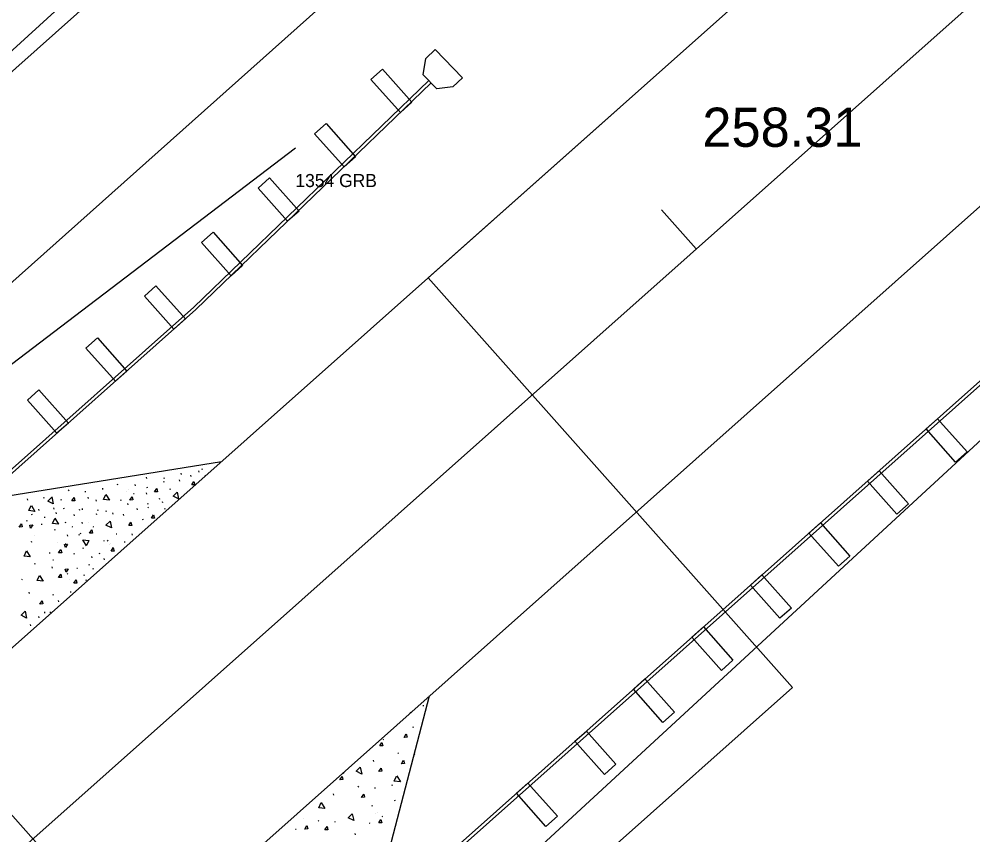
# Model space of a CAD drawing. Extents: x 49683 to 58852, y 49525 to 54803.
# Drawn here: x 53937.7 to 54010.8, y 51862.4 to 51924.9 of the extents above; entities that cross this region are included whole.
import ezdxf

# ---------------------------------------------------------------- set-up
doc = ezdxf.new("R2010")
doc.units = 0
for name, color, linetype in [('Level 1', 7, 'Continuous'), ('Level 11', 7, 'Continuous'), ('Level 13', 7, 'Continuous'), ('Level 15', 7, 'Continuous'), ('Level 18', 7, 'Continuous'), ('Level 19', 7, 'Continuous'), ('Level 20', 7, 'Continuous'), ('Level 27', 7, 'Continuous'), ('Level 3', 7, 'Continuous'), ('Level 32', 7, 'Continuous'), ('Level 57', 7, 'Continuous'), ('Level 7', 7, 'Continuous'), ('Level 8', 7, 'Continuous')]:
    doc.layers.add(name, color=color, linetype=linetype)

msp = doc.modelspace()

# ---------------------------------------------------------------- linework, layer by layer
at = {"layer": 'Level 1'}
msp.add_line((52544.807, 50683.302), (55534.583, 53340.862), dxfattribs=at)
at = {"layer": 'Level 11'}
msp.add_line((53944.235, 51830.768), (54450.301, 52297.6), dxfattribs=at)
at = {"layer": 'Level 13'}
for p, q in [((55279.532, 53069.998), (53969.027, 51905.114)), ((53996.93, 51873.722), (53969.027, 51905.114)), ((53681.554, 51593.39), (53996.93, 51873.722))]:
    msp.add_line(p, q, dxfattribs=at)
at = {"layer": 'Level 15'}
msp.add_line((53924.129, 51878.584), (53953.361, 51845.698), dxfattribs=at)
at = {"layer": 'Level 18'}
msp.add_line((53921.658, 51908.457), (53958.658, 51942.092), dxfattribs=at)
at = {"layer": 'Level 19'}
for p, q in [((52714.154, 50773.623), (54181.768, 52078.16)), ((53989.569, 51907.317), (53986.911, 51910.307))]:
    msp.add_line(p, q, dxfattribs=at)
at = {"layer": 'Level 20'}
for p, q in [((53930.772, 51871.11), (54173.795, 52087.129)), ((53946.717, 51853.172), (54189.74, 52069.191))]:
    msp.add_line(p, q, dxfattribs=at)
at = {"layer": 'Level 27'}
for p, q in [((53938.412, 51832.41), (54196.384, 52061.717)), ((53938.578, 51832.223), (54196.55, 52061.53)), ((53964.642, 51920.308), (53965.526, 51921.093)), ((53965.526, 51921.093), (53967.784, 51918.552)), ((53951.064, 51902.86), (53969.085, 51920.217)), ((53951.23, 51902.673), (53969.251, 51920.03)), ((53966.901, 51917.767), (53964.642, 51920.308)), ((53967.784, 51918.552), (53966.901, 51917.767)), ((53960.317, 51916.143), (53961.201, 51916.928)), ((53961.201, 51916.928), (53963.459, 51914.386)), ((53962.576, 51913.601), (53960.317, 51916.143)), ((53963.459, 51914.386), (53962.576, 51913.601)), ((53955.992, 51911.977), (53956.876, 51912.762)), ((53956.876, 51912.762), (53959.134, 51910.221)), ((53958.251, 51909.435), (53955.992, 51911.977)), ((53959.134, 51910.221), (53958.251, 51909.435)), ((53951.667, 51907.811), (53952.551, 51908.597)), ((53952.551, 51908.597), (53954.809, 51906.055)), ((53953.926, 51905.27), (53951.667, 51907.811)), ((53954.809, 51906.055), (53953.926, 51905.27)), ((53947.282, 51903.713), (53948.166, 51904.499)), ((53948.166, 51904.499), (53950.424, 51901.957)), ((53949.541, 51901.172), (53947.282, 51903.713)), ((53909.014, 51865.483), (53951.064, 51902.86)), ((53909.18, 51865.296), (53951.23, 51902.673)), ((53950.424, 51901.957), (53949.541, 51901.172)), ((53942.798, 51899.727), (53943.681, 51900.512)), ((53943.681, 51900.512), (53945.94, 51897.971)), ((53945.056, 51897.186), (53942.798, 51899.727)), ((53945.94, 51897.971), (53945.056, 51897.186)), ((53938.313, 51895.741), (53939.197, 51896.526)), ((53939.197, 51896.526), (53941.455, 51893.985)), ((53940.572, 51893.2), (53938.313, 51895.741)), ((54007.174, 51893.532), (54008.058, 51894.317)), ((54008.058, 51894.317), (54010.316, 51891.775)), ((53941.455, 51893.985), (53940.572, 51893.2)), ((54009.433, 51890.99), (54007.174, 51893.532)), ((54010.316, 51891.775), (54009.433, 51890.99)), ((54002.69, 51889.545), (54003.573, 51890.331)), ((54003.573, 51890.331), (54005.832, 51887.789)), ((54004.948, 51887.004), (54002.69, 51889.545)), ((54005.832, 51887.789), (54004.948, 51887.004)), ((53998.205, 51885.559), (53999.089, 51886.344)), ((53999.089, 51886.344), (54001.347, 51883.803)), ((54000.464, 51883.018), (53998.205, 51885.559)), ((54001.347, 51883.803), (54000.464, 51883.018)), ((53993.721, 51881.573), (53994.604, 51882.358)), ((53994.604, 51882.358), (53996.863, 51879.817)), ((53995.979, 51879.032), (53993.721, 51881.573)), ((53996.863, 51879.817), (53995.979, 51879.032)), ((53989.236, 51877.587), (53990.12, 51878.372)), ((53990.12, 51878.372), (53992.378, 51875.831)), ((53991.495, 51875.045), (53989.236, 51877.587)), ((53992.378, 51875.831), (53991.495, 51875.045)), ((53984.752, 51873.601), (53985.635, 51874.386)), ((53985.635, 51874.386), (53987.894, 51871.844)), ((53987.01, 51871.059), (53984.752, 51873.601)), ((53987.894, 51871.844), (53987.01, 51871.059)), ((53980.267, 51869.615), (53981.151, 51870.4)), ((53981.151, 51870.4), (53983.409, 51867.858)), ((53982.526, 51867.073), (53980.267, 51869.615)), ((53983.409, 51867.858), (53982.526, 51867.073)), ((53975.783, 51865.628), (53976.666, 51866.414)), ((53976.666, 51866.414), (53978.925, 51863.872)), ((53978.041, 51863.087), (53975.783, 51865.628)), ((53978.925, 51863.872), (53978.041, 51863.087))]:
    msp.add_line(p, q, dxfattribs=at)
msp.add_lwpolyline([(53970.926, 51919.74), (53969.686, 51919.582), (53968.642, 51920.658), (53968.837, 51921.893), (53969.555, 51922.589), (53971.644, 51920.436)], close=True, dxfattribs=at)
at = {"layer": 'Level 3'}
msp.add_line((53898.742, 51870.567), (54083.389, 52035.124), dxfattribs=at)
at = {"layer": 'Level 7'}
msp.add_line((53922.854, 51887.665), (53958.852, 51915.059), dxfattribs=at)
at = {"layer": 'Level 8'}
for p, q in [((53935.625, 51888.219), (53953.195, 51891.04)), ((53951.692, 51890.508), (53951.717, 51890.42)), ((53947.407, 51889.839), (53947.431, 51889.752)), ((53948.779, 51889.828), (53948.803, 51889.74)), ((53950.065, 51890.146), (53950.09, 51890.058)), ((53950.818, 51889.99), (53950.842, 51889.902)), ((53951.433, 51890.314), (53951.458, 51890.226)), ((53951.98, 51889.935), (53951.916, 51889.955)), ((53944.059, 51888.987), (53944.083, 51888.9)), ((53945.205, 51889.332), (53945.23, 51889.244)), ((53946.545, 51889.277), (53946.569, 51889.189)), ((53947.471, 51889.1), (53947.496, 51889.012)), ((53948.738, 51889.545), (53948.763, 51889.458)), ((53949.232, 51888.985), (53949.256, 51888.897)), ((53949.944, 51889.633), (53949.968, 51889.545)), ((53939.549, 51888.32), (53939.573, 51888.232)), ((53941.504, 51888.801), (53941.444, 51888.86)), ((53942.79, 51888.71), (53942.726, 51888.729)), ((53942.951, 51888.305), (53942.976, 51888.217)), ((53945.937, 51888.773), (53945.937, 51888.773)), ((53946.066, 51888.879), (53946.066, 51888.879)), ((53946.503, 51888.557), (53946.439, 51888.576)), ((53947.419, 51888.629), (53947.443, 51888.541)), ((53938.29, 51888.175), (53938.314, 51888.087)), ((53940.867, 51888.166), (53940.892, 51888.078)), ((53943.554, 51888.096), (53943.578, 51888.008)), ((53945.519, 51888.053), (53945.456, 51888.072)), ((53945.994, 51887.819), (53946.019, 51887.731)), ((53947.516, 51887.851), (53947.54, 51887.763)), ((53947.604, 51887.486), (53947.544, 51887.545)), ((53948.422, 51888.24), (53948.447, 51888.152)), ((53948.649, 51887.981), (53948.673, 51887.893)), ((53938.643, 51887.037), (53938.667, 51886.949)), ((53939.216, 51887.291), (53939.189, 51887.378)), ((53939.614, 51886.81), (53939.638, 51886.723)), ((53940.317, 51887.485), (53940.341, 51887.397)), ((53940.557, 51887.039), (53940.53, 51887.126)), ((53941.074, 51887.495), (53941.098, 51887.407)), ((53941.883, 51886.976), (53941.907, 51886.888)), ((53942.271, 51887.397), (53942.296, 51887.309)), ((53942.501, 51887.431), (53942.525, 51887.343)), ((53943.586, 51887.059), (53943.611, 51886.971)), ((53943.696, 51887.365), (53943.72, 51887.277)), ((53944.317, 51887.299), (53944.341, 51887.211)), ((53944.829, 51887.106), (53944.853, 51887.018)), ((53945.649, 51887.005), (53945.673, 51886.917)), ((53946.707, 51887.43), (53946.731, 51887.342)), ((53948.89, 51887.395), (53948.826, 51887.414)), ((53938.254, 51886.551), (53938.278, 51886.463)), ((53939.379, 51886.247), (53939.443, 51886.23)), ((53941.2, 51886.422), (53941.224, 51886.334)), ((53941.716, 51886.066), (53941.781, 51886.048)), ((53942.498, 51886.393), (53942.522, 51886.305)), ((53942.977, 51886.338), (53942.977, 51886.338)), ((53947.127, 51886.652), (53947.152, 51886.564)), ((53938.859, 51885.404), (53938.859, 51885.404)), ((53940.456, 51885.749), (53940.429, 51885.836)), ((53941.362, 51885.417), (53941.386, 51885.329)), ((53942.268, 51885.482), (53942.293, 51885.394)), ((53942.43, 51885.512), (53942.366, 51885.531)), ((53943.413, 51886.016), (53943.349, 51886.035)), ((53945.106, 51885.514), (53945.17, 51885.497)), ((53946.378, 51885.404), (53946.351, 51885.491)), ((53938.596, 51884.945), (53938.62, 51884.858)), ((53940.603, 51884.837), (53940.603, 51884.837)), ((53941.228, 51884.758), (53941.252, 51884.67)), ((53944.139, 51884.98), (53944.204, 51884.962)), ((53944.515, 51884.945), (53944.455, 51885.004)), ((53944.586, 51884.671), (53944.586, 51884.671)), ((53944.711, 51884.781), (53944.711, 51884.781)), ((53945.801, 51884.854), (53945.737, 51884.873)), ((53940.056, 51884.011), (53939.992, 51884.03)), ((53941.936, 51883.921), (53941.909, 51884.008)), ((53942.56, 51884.464), (53942.584, 51884.376)), ((53943.822, 51884.056), (53943.847, 51883.968)), ((53944.878, 51884.372), (53944.851, 51884.459)), ((53938.854, 51883.257), (53938.878, 51883.169)), ((53940.324, 51883.475), (53940.26, 51883.494)), ((53943.013, 51883.181), (53943.037, 51883.093)), ((53943.276, 51883.669), (53943.249, 51883.756)), ((53944.178, 51883.602), (53944.203, 51883.514)), ((53940.186, 51882.963), (53940.21, 51882.875)), ((53941.426, 51882.405), (53941.365, 51882.463)), ((53942.098, 51882.877), (53942.163, 51882.86)), ((53943.37, 51882.767), (53943.343, 51882.854)), ((53937.95, 51881.974), (53937.886, 51881.993)), ((53941.578, 51882.034), (53941.578, 51882.034)), ((53942.711, 51882.313), (53942.648, 51882.333)), ((53942.786, 51882.015), (53942.811, 51881.927)), ((53938.423, 51881.022), (53938.447, 51880.934)), ((53941.607, 51881.089), (53941.631, 51881.001)), ((53940.338, 51880.812), (53940.274, 51880.831)), ((53940.682, 51880.394), (53940.706, 51880.306)), ((53939.614, 51879.519), (53939.638, 51879.431)), ((53940.049, 51879.532), (53940.073, 51879.445)), ((53939.16, 51879.163), (53939.185, 51879.075)), ((53938.517, 51878.549), (53938.541, 51878.461)), ((53964.572, 51855.663), (53969.139, 51873.103)), ((53968.685, 51872.317), (53968.621, 51872.336)), ((53967.709, 51871.799), (53967.645, 51871.817)), ((53967.855, 51870.753), (53967.88, 51870.665)), ((53965.634, 51869.73), (53965.57, 51869.749)), ((53966.752, 51868.677), (53966.691, 51868.734)), ((53968.039, 51868.605), (53967.975, 51868.623)), ((53964.804, 51868.166), (53964.829, 51868.078)), ((53962.583, 51867.143), (53962.519, 51867.162)), ((53963.701, 51866.09), (53963.64, 51866.147)), ((53964.988, 51866.018), (53964.924, 51866.036)), ((53966.253, 51866.314), (53966.278, 51866.226)), ((53961.753, 51865.579), (53961.779, 51865.491)), ((53966.446, 51865.134), (53966.472, 51865.047)), ((53964.718, 51864.734), (53964.744, 51864.646)), ((53965.12, 51864.154), (53965.12, 51864.154)), ((53959.446, 51863.684), (53959.446, 51863.684)), ((53960.65, 51863.503), (53960.589, 51863.56)), ((53961.937, 51863.43), (53961.873, 51863.449)), ((53964.993, 51864.046), (53964.993, 51864.046)), ((53965.562, 51863.838), (53965.497, 51863.856)), ((53958.912, 51862.85), (53958.847, 51862.868)), ((53964.586, 51863.32), (53964.522, 51863.338)), ((53963.395, 51862.547), (53963.421, 51862.46))]:
    msp.add_line(p, q, dxfattribs=at)
for points in [[(53951.077, 51889.504), (53951.138, 51889.255), (53950.907, 51889.245), (53951.077, 51889.504)], [(53940.189, 51888.324), (53940.296, 51887.801), (53939.87, 51888.013), (53940.182, 51888.318)], [(53941.887, 51888.279), (53941.948, 51888.03), (53941.717, 51888.019), (53941.887, 51888.279)], [(53944.334, 51888.526), (53944.613, 51888.071), (53944.14, 51888.125), (53944.329, 51888.518)], [(53946.345, 51888.343), (53946.406, 51888.094), (53946.175, 51888.084), (53946.345, 51888.343)], [(53948.222, 51888.974), (53948.283, 51888.725), (53948.052, 51888.714), (53948.222, 51888.974)], [(53949.792, 51888.698), (53949.899, 51888.175), (53949.473, 51888.387), (53949.785, 51888.692)], [(53938.619, 51887.679), (53938.898, 51887.224), (53938.425, 51887.278), (53938.614, 51887.671)], [(53947.987, 51886.963), (53948.049, 51886.714), (53947.818, 51886.704), (53947.987, 51886.963)], [(53937.86, 51886.274), (53937.921, 51886.025), (53937.69, 51886.015), (53937.86, 51886.274)], [(53938.563, 51885.931), (53938.494, 51886.178), (53938.725, 51886.196), (53938.563, 51885.931)], [(53940.421, 51886.696), (53940.7, 51886.242), (53940.227, 51886.295), (53940.417, 51886.688)], [(53944.655, 51886.483), (53944.762, 51885.96), (53944.336, 51886.172), (53944.648, 51886.477)], [(53946.253, 51886.393), (53946.314, 51886.144), (53946.083, 51886.133), (53946.253, 51886.393)], [(53943.255, 51885.802), (53943.316, 51885.553), (53943.085, 51885.543), (53943.255, 51885.802)], [(53941.234, 51884.444), (53941.165, 51884.691), (53941.395, 51884.708), (53941.234, 51884.444)], [(53942.845, 51884.591), (53942.552, 51885.037), (53943.026, 51884.998), (53942.849, 51884.599)], [(53938.252, 51884.201), (53938.531, 51883.746), (53938.058, 51883.8), (53938.247, 51884.193)], [(53940.881, 51884.301), (53940.942, 51884.052), (53940.711, 51884.042), (53940.881, 51884.301)], [(53944.898, 51884.423), (53944.959, 51884.174), (53944.728, 51884.163), (53944.898, 51884.423)], [(53940.871, 51882.418), (53940.932, 51882.169), (53940.701, 51882.159), (53940.871, 51882.418)], [(53941.283, 51882.561), (53941.214, 51882.808), (53941.444, 51882.826), (53941.283, 51882.561)], [(53939.256, 51882.322), (53939.535, 51881.867), (53939.062, 51881.921), (53939.251, 51882.314)], [(53942.044, 51881.984), (53942.105, 51881.735), (53941.874, 51881.725), (53942.044, 51881.984)], [(53939.435, 51880.381), (53939.496, 51880.132), (53939.265, 51880.121), (53939.435, 51880.381)], [(53938.15, 51879.574), (53938.257, 51879.051), (53937.83, 51879.264), (53938.143, 51879.568)], [(53967.347, 51870.173), (53967.412, 51869.925), (53967.181, 51869.911), (53967.347, 51870.173)], [(53965.479, 51869.515), (53965.544, 51869.266), (53965.313, 51869.253), (53965.479, 51869.515)], [(53967.143, 51868.16), (53967.208, 51867.912), (53966.977, 51867.898), (53967.143, 51868.16)], [(53963.818, 51867.629), (53963.933, 51867.107), (53963.503, 51867.313), (53963.811, 51867.623)], [(53965.417, 51867.563), (53965.482, 51867.315), (53965.251, 51867.301), (53965.417, 51867.563)], [(53962.428, 51866.928), (53962.493, 51866.679), (53962.263, 51866.666), (53962.428, 51866.928)], [(53966.615, 51866.96), (53966.901, 51866.509), (53966.427, 51866.556), (53966.61, 51866.952)], [(53960.833, 51864.924), (53961.119, 51864.473), (53960.645, 51864.52), (53960.828, 51864.916)], [(53964.092, 51865.573), (53964.157, 51865.325), (53963.926, 51865.311), (53964.092, 51865.573)], [(53963.214, 51864.064), (53963.328, 51863.543), (53962.899, 51863.749), (53963.206, 51864.058)], [(53965.407, 51863.622), (53965.472, 51863.374), (53965.241, 51863.36), (53965.407, 51863.622)], [(53959.732, 51863.152), (53959.797, 51862.904), (53959.566, 51862.89), (53959.732, 51863.152)], [(53961.275, 51863.091), (53961.34, 51862.843), (53961.109, 51862.83), (53961.275, 51863.091)]]:
    msp.add_lwpolyline(points, dxfattribs=at)

# ---------------------------------------------------------------- texts
at = {"layer": 'Level 32'}
msp.add_text('258.31', height=3, dxfattribs=at).set_placement((53990.033, 51915.141))
at = {"layer": 'Level 57'}
msp.add_text('1354 GRB', height=1, dxfattribs=at).set_placement((53958.852, 51912.059))

doc.saveas('drawing.dxf')
